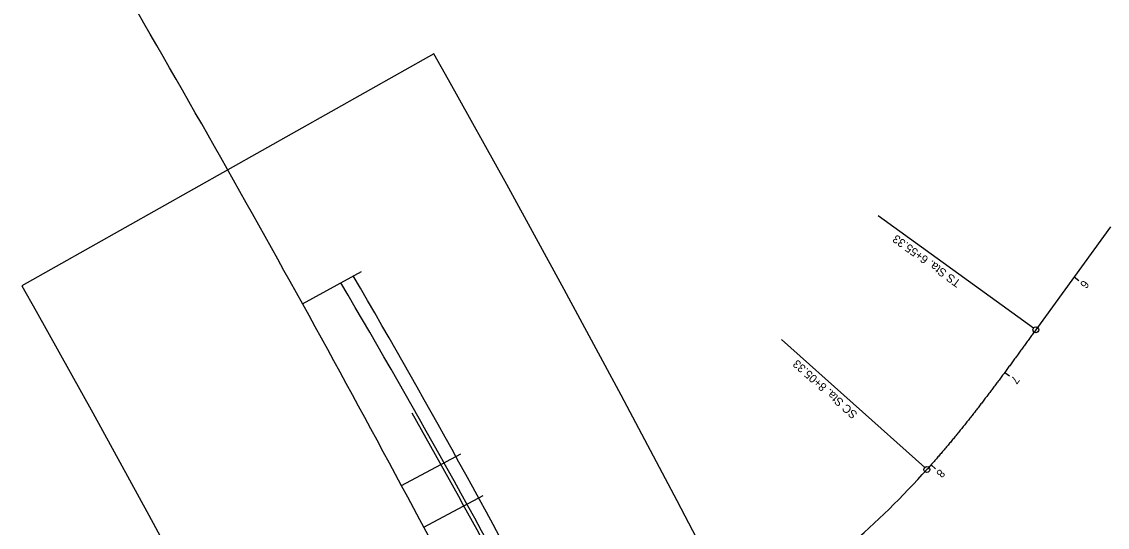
# Model space of a CAD drawing. Extents: x 21904 to 36537, y 12187 to 32963.
# Drawn here: x 23873 to 24791, y 28596 to 29025 of the extents above; entities that cross this region are included whole.
import ezdxf

# ---------------------------------------------------------------- set-up
doc = ezdxf.new("R2010")
doc.units = 0
for name, color, linetype in [('BR_X_Beam_Centerline', 7, 'Continuous'), ('BR_X_Dia_Centerline', 7, 'Continuous'), ('BR_X_Gen_Approach_Slab', 7, 'Continuous'), ('BR_X_Sub_Object', 7, 'Continuous'), ('GE_X_CL_50', 7, 'Continuous'), ('PM_X_Channelizing_Line', 7, 'Continuous')]:
    doc.layers.add(name, color=color, linetype=linetype)

msp = doc.modelspace()

# ---------------------------------------------------------------- linework, layer by layer
at = {"layer": 'BR_X_Beam_Centerline'}
for p, q in [((24110.27, 28785.6), (24160.17, 28813.14)), ((24193.89, 28631.88), (24244.13, 28658.81)), ((24212.74, 28596.6), (24263.06, 28623.39))]:
    msp.add_line(p, q, dxfattribs=at)
at = {"layer": 'BR_X_Dia_Centerline'}
msp.add_arc((11569.81, 21863.73), 14323.94, 27.320833, 30.120833, dxfattribs=at)
at = {"layer": 'BR_X_Gen_Approach_Slab'}
msp.add_arc((18135.2, 25260.67), 6971.31, 27.373526, 29.496041, dxfattribs=at)
at = {"layer": 'BR_X_Sub_Object'}
for centre, radius, start, end in [((18135.2, 25260.67), 6974.31, 27.357089, 30.529372), ((17498.11, 24931.04), 7702.63, 27.35709, 30.231556)]:
    msp.add_arc(centre, radius, start, end, dxfattribs=at)
at = {"layer": 'GE_X_CL_50'}
for p, q in [((24728.34, 28765.14), (24597, 28860.2)), ((24793.44, 28850.81), (24730.37, 28763.67)), ((24762.81, 28808.5), (24766.86, 28805.56)), ((24636.42, 28647.03), (24515.44, 28755.56)), ((24704.07, 28727.57), (24708.09, 28724.6)), ((24641.83, 28649.34), (24645.57, 28646.03))]:
    msp.add_line(p, q, dxfattribs=at)
for centre in [(24730.37, 28763.67), (24638.28, 28645.36)]:
    msp.add_circle(centre, 2.5, dxfattribs=at)
msp.add_arc((24105.17, 29123.62), 716.2, 303.32083, 318.10417, dxfattribs=at)
msp.add_spline([(24730.37, 28763.67), (24729.18, 28762.03), (24727.99, 28760.39), (24726.8, 28758.75), (24725.61, 28757.1), (24724.43, 28755.46), (24723.24, 28753.82), (24722.05, 28752.18), (24720.86, 28750.54), (24719.67, 28748.9), (24718.47, 28747.26), (24717.28, 28745.62), (24716.09, 28743.98), (24714.9, 28742.34), (24713.7, 28740.7), (24712.51, 28739.07), (24711.31, 28737.43), (24710.11, 28735.79), (24708.92, 28734.16), (24707.72, 28732.52), (24706.52, 28730.89), (24705.31, 28729.26), (24704.11, 28727.63), (24702.91, 28726), (24701.7, 28724.37), (24700.49, 28722.74), (24699.29, 28721.11), (24698.07, 28719.49), (24696.86, 28717.86), (24695.65, 28716.24), (24694.43, 28714.62), (24693.22, 28713), (24692, 28711.38), (24690.77, 28709.76), (24689.55, 28708.14), (24688.33, 28706.53), (24687.1, 28704.91), (24685.87, 28703.3), (24684.64, 28701.69), (24683.4, 28700.09), (24682.16, 28698.48), (24680.93, 28696.88), (24679.68, 28695.27), (24678.44, 28693.67), (24677.19, 28692.08), (24675.94, 28690.48), (24674.69, 28688.89), (24673.43, 28687.29), (24672.18, 28685.71), (24670.91, 28684.12), (24669.65, 28682.53), (24668.38, 28680.95), (24667.11, 28679.37), (24665.84, 28677.8), (24664.56, 28676.22), (24663.28, 28674.65), (24662, 28673.08), (24660.71, 28671.51), (24659.42, 28669.95), (24658.13, 28668.39), (24656.83, 28666.83), (24655.53, 28665.28), (24654.23, 28663.72), (24652.92, 28662.17), (24651.61, 28660.63), (24650.3, 28659.09), (24648.98, 28657.55), (24647.65, 28656.01), (24646.33, 28654.48), (24645, 28652.95), (24643.66, 28651.43), (24642.32, 28649.9), (24640.98, 28648.38), (24639.63, 28646.87), (24638.28, 28645.36)], degree=3, dxfattribs=at)
at = {"layer": 'PM_X_Channelizing_Line'}
msp.add_line((24221.14, 28997.36), (23872.72, 28800.89), dxfattribs=at)
for points in [[(24331.63, 28797.76), (24282.91, 28886.69), (24233.57, 28975.27), (24221.14, 28997.36)], [(23872.72, 28800.89), (23884.8, 28779.41), (23932.78, 28693.27), (23980.16, 28606.79)], [(23980.16, 28606.79), (24026.93, 28519.99), (24073.1, 28432.86), (24118.23, 28346.23), (24118.66, 28345.4), (24164.56, 28256.55), (24210.46, 28167.71), (24256.35, 28078.86), (24611.73, 28262.45), (24565.84, 28351.3), (24519.94, 28440.14), (24474.04, 28528.99), (24473.61, 28529.82), (24427.2, 28618.9), (24379.73, 28708.5), (24331.63, 28797.76)]]:
    msp.add_lwpolyline(points, dxfattribs=at)

# ---------------------------------------------------------------- texts
at = {"layer": 'GE_X_CL_50'}
for s, rotation, p in [('TS Sta. 6+55.33', 144.10417, (24667.56, 28804.81)), ('6', 234.10417, (24770.47, 28806.29)), ('SC Sta. 8+05.33', 138.10417, (24580.12, 28692.84)), ('7', 233.57211, (24711.79, 28725.4)), ('8', 228.52316, (24649.12, 28646.27))]:
    msp.add_text(s, height=7, rotation=rotation, dxfattribs=at).set_placement(p)

doc.saveas('drawing.dxf')
